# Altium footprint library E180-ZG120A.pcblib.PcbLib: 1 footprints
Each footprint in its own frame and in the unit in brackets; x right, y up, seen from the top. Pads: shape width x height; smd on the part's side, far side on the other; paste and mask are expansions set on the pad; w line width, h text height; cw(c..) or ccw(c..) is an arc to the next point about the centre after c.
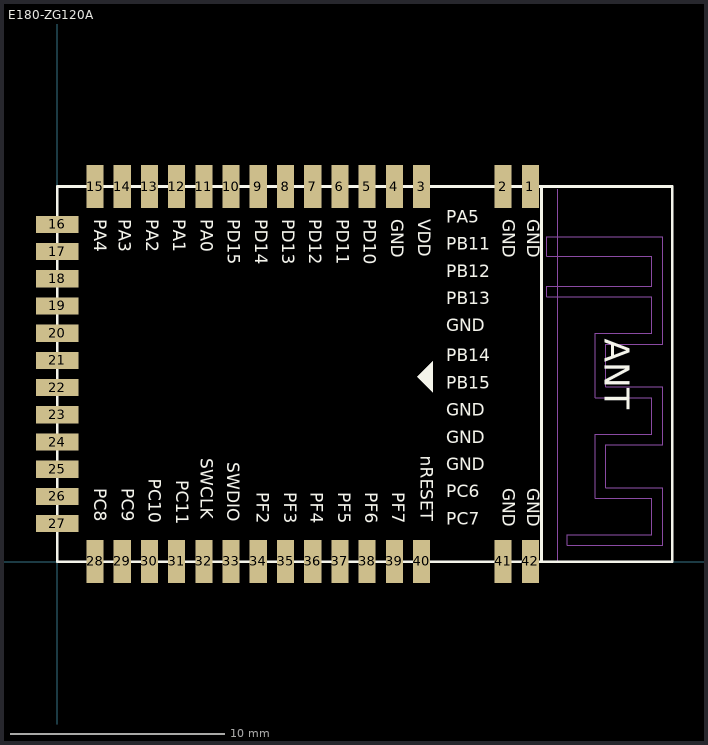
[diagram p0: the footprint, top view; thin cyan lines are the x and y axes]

## E180-ZG120A [mm] "28.7mm*17.5mm*2.60mm-S"
pads (42):
  rect 0.8x2 smd: 1(22.081,17.517) 2(20.811,17.517) 3(17.001,17.517) 4(15.731,17.517) 5(14.461,17.517) 6(13.191,17.517) 7(11.921,17.517) 8(10.651,17.517) 9(9.381,17.517) 10(8.111,17.517) 11(6.841,17.517) 12(5.571,17.517) 13(4.301,17.517) 14(3.031,17.517) 15(1.761,17.517) 28(1.761,0.017) 29(3.031,0.017) 30(4.301,0.017) 31(5.571,0.017) 32(6.841,0.017) 33(8.111,0.017) 34(9.381,0.017) 35(10.651,0.017) 36(11.921,0.017) 37(13.191,0.017) 38(14.461,0.017) 39(15.731,0.017) 40(17.001,0.017) 41(20.811,0.017) 42(22.081,0.017)
  rect 2x0.8 smd: 16(-0.004,15.752) 17(-0.004,14.482) 18(-0.004,13.212) 19(-0.004,11.942) 20(-0.004,10.672) 21(-0.004,9.402) 22(-0.004,8.132) 23(-0.004,6.862) 24(-0.004,5.592) 25(-0.004,4.322) 26(-0.004,3.052) 27(-0.004,1.782)
Top Overlay:
  region: 17.526,7.907 16.797,8.636 17.526,9.365
  lines w0.127: 22.604,0 22.604,17.52 ; 0,0 0,17.52 28.7,17.52 28.7,0 0,0
  text "GND" at 21.717,16.002 h1
  text "GND" at 20.574,16.002 h1
  text "PA4" at 1.524,16.002 h1
  text "PA3" at 2.667,16.002 h1
  text "PA2" at 3.937,16.002 h1
  text "PA1" at 5.207,16.002 h1
  text "PA0" at 6.477,16.002 h1
  text "PD15" at 7.747,16.002 h1
  text "PD14" at 9.017,16.002 h1
  text "PD13" at 10.287,16.002 h1
  text "PD12" at 11.557,16.002 h1
  text "PD11" at 12.827,16.002 h1
  text "PD10" at 14.097,16.002 h1
  text "GND" at 15.367,16.002 h1
  text "VDD" at 16.637,16.002 h1
  text "nRESET" at 16.764,4.953 h1
  text "PF7" at 15.418,3.249 h1
  text "PF6" at 14.157,3.249 h1
  text "PF5" at 12.896,3.249 h1
  text "PF4" at 11.623,3.249 h1
  text "PF3" at 10.374,3.249 h1
  text "PF2" at 9.101,3.249 h1
  text "SWDIO" at 7.725,4.646 h1
  text "SWCLK" at 6.477,4.826 h1
  text "PC11" at 5.334,3.81 h1
  text "PC10" at 4.069,3.884 h1
  text "PC9" at 2.794,3.429 h1
  text "PC8" at 1.524,3.429 h1
  text "ANT" at 25.146,10.414 h2
  text "PA5" at 18.161,15.621 h1
  text "PB11" at 18.161,14.351 h1
  text "PB12" at 18.161,13.081 h1
  text "PB13" at 18.161,11.811 h1
  text "GND" at 18.161,10.541 h1
  text "PB14" at 18.161,9.144 h1
  text "PB15" at 18.161,7.874 h1
  text "GND" at 18.161,6.604 h1
  text "GND" at 18.161,5.334 h1
  text "GND" at 18.161,4.064 h1
  text "PC6" at 18.161,2.794 h1
  text "PC7" at 18.161,1.524 h1
  text "GND" at 20.574,3.429 h1
  text "GND" at 21.717,3.429 h1
Mechanical 3:
  lines w0.005: 23.348,11.764 23.348,12.264 ; 24.744,0.764 28.248,0.764 ; 25.108,5.464 25.108,5.964 ; 27.748,0.764 23.808,0.764 23.808,1.264 27.748,1.264 27.748,2.964 25.108,2.964 25.108,5.964 ; 23.348,14.264 27.748,14.264 ; 23.348,14.264 23.348,15.164 ; 23.348,14.264 22.848,14.264 22.848,15.164 23.348,15.164 ; 23.348,15.164 27.748,15.164 28.248,15.164 28.248,10.164 27.748,10.164 25.608,10.164 25.608,8.164 28.248,8.164 ; 25.108,5.964 27.748,5.964 27.748,7.664 25.108,7.664 25.108,8.164 25.108,10.164 25.108,10.664 27.748,10.664 27.748,12.364 22.848,12.364 22.848,12.864 27.748,12.864 ; 25.608,3.464 25.608,5.464 ; 25.608,3.464 28.248,3.464 ; 25.608,3.464 25.608,5.464 ; 25.608,5.464 28.248,5.464 ; 27.748,12.864 27.748,14.264 ; 27.748,12.864 27.748,14.264 ; 28.248,0.764 28.248,3.464 ; 28.248,0.764 28.248,3.464 ; 28.248,5.464 28.248,8.164 ; 28.248,5.464 28.248,8.164
Mechanical 4:
  lines w0.005: 23.348,-0.047 23.348,17.4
